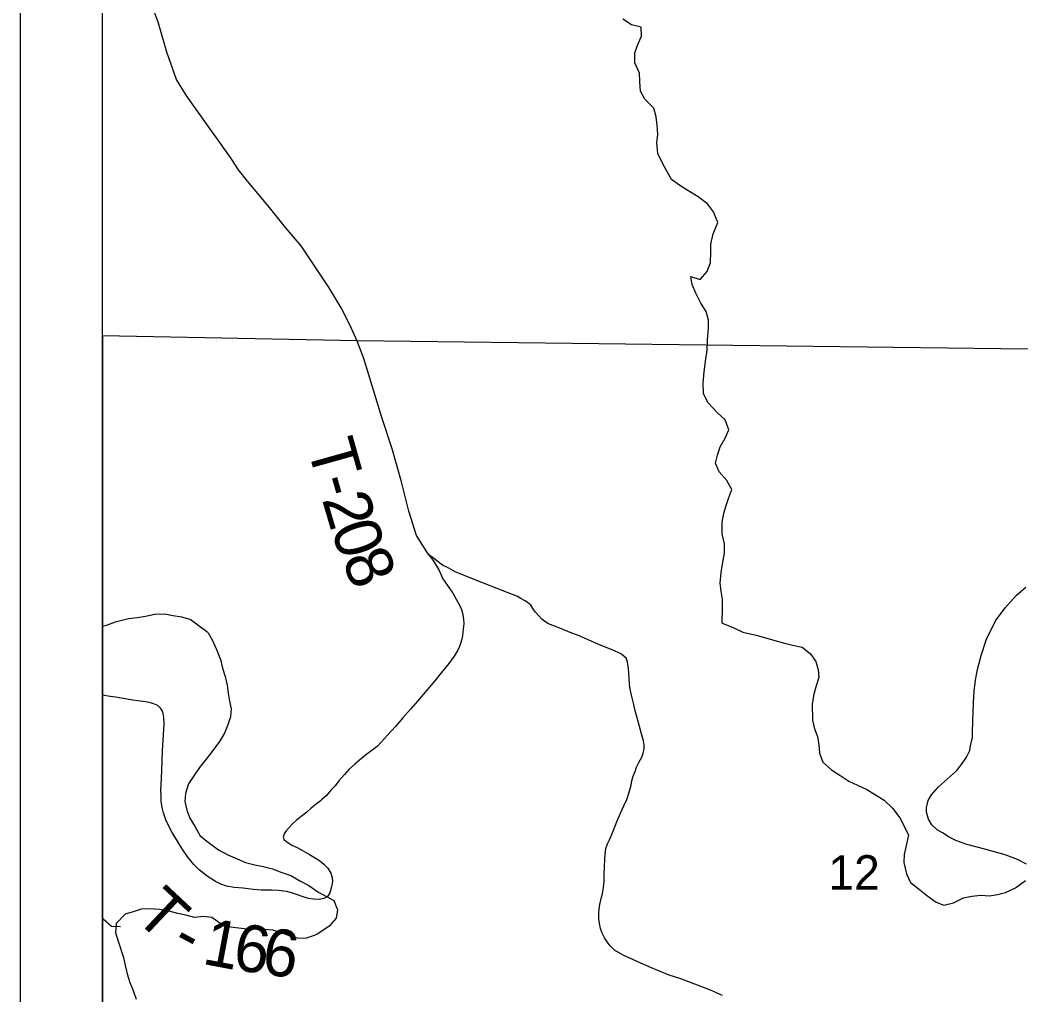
# Model space of a CAD drawing. Extents: x 0 to 34, y 0 to 22.
# Drawn here: x 2 to 3.211, y 14.917 to 16.097 of the extents above; entities that cross this region are included whole.
import ezdxf

# ---------------------------------------------------------------- set-up
doc = ezdxf.new("R2010")
doc.units = 0
for name, color, linetype in [('GM_X_Corporation', 7, 'Continuous'), ('GM_X_Minor_River', 7, 'Continuous'), ('GM_X_Section_Text', 7, 'Continuous'), ('GM_X_State_Route', 7, 'Continuous'), ('GM_X_Township_Road', 7, 'Continuous'), ('GM_X_Township_Road_Text', 7, 'Continuous'), ('SH_Data', 7, 'Continuous')]:
    doc.layers.add(name, color=color, linetype=linetype)

msp = doc.modelspace()

# ---------------------------------------------------------------- linework, layer by layer
at = {"layer": 'GM_X_Corporation'}
msp.add_lwpolyline([(2.1, 15.7148), (2.1, 14.1), (4.5503, 14.1), (4.5507, 14.1138), (4.5505, 14.2449), (4.5614, 14.6695), (4.5616, 14.6767), (4.5617, 14.6817), (4.5685, 14.9157), (4.5738, 15.1325), (4.5873, 15.6794), (4.2138, 15.6834), (3.9277, 15.6898), (3.3171, 15.6975), (2.4078, 15.7088)], close=True, dxfattribs=at)
at = {"layer": 'GM_X_Minor_River'}
for points in [[(2.8496, 15.3671), (2.8501, 15.386), (2.8499, 15.3963), (2.8483, 15.4058), (2.8474, 15.4156), (2.8484, 15.4282), (2.8505, 15.4408), (2.8526, 15.4518), (2.8525, 15.4632), (2.8496, 15.4754), (2.8498, 15.4894), (2.8516, 15.5001), (2.8545, 15.5096), (2.8578, 15.5192), (2.8615, 15.5287), (2.8552, 15.5397), (2.846, 15.5502), (2.8416, 15.5608), (2.8438, 15.5703), (2.8474, 15.5806), (2.8534, 15.591), (2.8578, 15.6013), (2.8531, 15.6134), (2.8435, 15.622), (2.8327, 15.6336), (2.8272, 15.6446), (2.8266, 15.6579), (2.828, 15.6712), (2.8293, 15.6838), (2.8314, 15.6975), (2.832, 15.7104), (2.833, 15.7237), (2.8332, 15.734), (2.8304, 15.7442), (2.8238, 15.7544), (2.8179, 15.7665), (2.8132, 15.7771), (2.8119, 15.7866), (2.823, 15.7829), (2.8313, 15.7929), (2.8357, 15.8036), (2.8359, 15.8162), (2.8358, 15.8257), (2.8386, 15.8383), (2.8442, 15.852), (2.8391, 15.8649), (2.8317, 15.8747), (2.8205, 15.8832), (2.8094, 15.8899), (2.7983, 15.897), (2.7883, 15.9041), (2.7778, 15.9233), (2.7719, 15.9358), (2.7706, 15.9491), (2.7716, 15.9586), (2.771, 15.97), (2.7698, 15.9802), (2.767, 15.9905), (2.7562, 16.0013), (2.7507, 16.0111), (2.7502, 16.0229), (2.7497, 16.0328), (2.7438, 16.0453), (2.744, 16.0574), (2.7477, 16.0674), (2.7521, 16.0777), (2.7516, 16.0887), (2.7401, 16.0912), (2.7294, 16.0983)], [(2.2276, 15.3555), (2.2168, 15.3636), (2.2057, 15.3714), (2.1958, 15.3744), (2.1851, 15.3761), (2.1752, 15.3779), (2.163, 15.3777), (2.152, 15.3753), (2.1417, 15.3736), (2.1311, 15.3723), (2.1152, 15.3683), (2.1053, 15.3648), (2.1, 15.3631)], [(2.8496, 15.3671), (2.8629, 15.3619), (2.8747, 15.3563), (2.8907, 15.3526), (2.901, 15.3496), (2.9135, 15.3459), (2.925, 15.343), (2.9349, 15.3404), (2.9463, 15.3382), (2.9562, 15.3303), (2.9631, 15.3205), (2.9659, 15.3106), (2.9667, 15.3011), (2.9634, 15.2912), (2.9604, 15.2813), (2.9586, 15.2695), (2.9588, 15.2498), (2.9612, 15.2391), (2.9651, 15.2297), (2.9667, 15.2198), (2.9675, 15.2096), (2.9714, 15.1989), (2.9821, 15.1895), (2.9932, 15.1824), (3.0031, 15.1756), (3.0134, 15.1708), (3.0245, 15.1655), (3.034, 15.1599), (3.0455, 15.1528), (3.0558, 15.143), (3.0647, 15.1313), (3.0751, 15.1108), (3.0725, 15.0994), (3.07, 15.0869), (3.0693, 15.0774), (3.0725, 15.0637), (3.0775, 15.0531), (3.0886, 15.0448), (3.0985, 15.0366), (3.1085, 15.0294), (3.118, 15.0257), (3.1294, 15.0284), (3.1415, 15.0346), (3.1517, 15.0366), (3.1627, 15.0378), (3.173, 15.0371), (3.1829, 15.0384), (3.1923, 15.0411), (3.2044, 15.0465), (3.2165, 15.0554)], [(2.2276, 15.3555), (2.2328, 15.3459), (2.2378, 15.3353), (2.2425, 15.3231), (2.2452, 15.3125), (2.2483, 15.3023), (2.2507, 15.292), (2.2519, 15.2822), (2.2535, 15.2727), (2.2555, 15.2632), (2.2548, 15.2537), (2.2515, 15.2438), (2.2474, 15.2339), (2.2414, 15.2239), (2.2335, 15.2129), (2.2252, 15.2025), (2.217, 15.1922), (2.2102, 15.1823), (2.2038, 15.1724), (2.2001, 15.1609), (2.1995, 15.151), (2.2018, 15.1408), (2.2053, 15.1309), (2.2119, 15.1204), (2.2181, 15.1098), (2.2276, 15.1019), (2.2402, 15.0928), (2.2513, 15.0868), (2.2627, 15.0816), (2.273, 15.0775), (2.2841, 15.0746), (2.2944, 15.0724), (2.3054, 15.0698), (2.3168, 15.0653), (2.3275, 15.0616), (2.3393, 15.0548), (2.3496, 15.0496), (2.3603, 15.0417), (2.3699, 15.0365), (2.3798, 15.0312), (2.3841, 15.0202), (2.3826, 15.01), (2.374, 15.0004), (2.3593, 14.99), (2.3468, 14.9857), (2.3373, 14.9853), (2.3278, 14.9879), (2.3167, 14.992), (2.306, 14.9953), (2.2954, 14.9964), (2.2829, 14.9966), (2.2718, 14.9969), (2.2612, 14.9984), (2.2517, 14.9994), (2.2418, 15.0039), (2.2322, 15.0107), (2.2219, 15.0121), (2.2113, 15.0109), (2.2006, 15.0135), (2.1911, 15.0157), (2.1805, 15.0186), (2.1687, 15.0205), (2.1565, 15.0211), (2.1466, 15.0207), (2.1368, 15.0175), (2.1273, 15.0148), (2.1164, 15.0033), (2.1157, 14.9927), (2.1189, 14.9821), (2.1251, 14.9624), (2.1271, 14.9525), (2.1298, 14.9426), (2.133, 14.932), (2.1368, 14.9222), (2.1404, 14.9119)], [(2.1, 15.0097), (2.1008, 15.009), (2.1108, 15.0004), (2.1216, 14.9997)]]:
    msp.add_lwpolyline(points, dxfattribs=at)
at = {"layer": 'GM_X_State_Route'}
msp.add_lwpolyline([(3.2178, 15.0755), (3.207, 15.0811), (3.1919, 15.0868), (3.1676, 15.0934), (3.1455, 15.0991), (3.1325, 15.1038), (3.1242, 15.1081), (3.1162, 15.1131), (3.1098, 15.1169), (3.1033, 15.1231), (3.0992, 15.1297), (3.0969, 15.1382), (3.0969, 15.1439), (3.0987, 15.1525), (3.103, 15.1594), (3.1116, 15.169), (3.1224, 15.1785), (3.133, 15.1883), (3.1393, 15.1961), (3.1454, 15.205), (3.1493, 15.213), (3.1502, 15.2185), (3.1526, 15.2286), (3.1526, 15.2356), (3.153, 15.2481), (3.1537, 15.2709), (3.1544, 15.2846), (3.156, 15.2981), (3.1584, 15.311), (3.1632, 15.3278), (3.1696, 15.3478), (3.1803, 15.3699), (3.192, 15.3855), (3.2057, 15.4009), (3.2169, 15.4107)], dxfattribs=at)
at = {"layer": 'GM_X_Township_Road'}
for points in [[(2.2547, 15.9306), (2.2109, 15.9927), (2.2009, 16.0061), (2.1892, 16.0253), (2.1777, 16.0582), (2.1677, 16.0933), (2.163, 16.1054), (2.1612, 16.1152), (2.1612, 16.1267), (2.1621, 16.1357), (2.1695, 16.1735), (2.1833, 16.2247), (2.1943, 16.2722), (2.1958, 16.2895), (2.195, 16.3043), (2.1869, 16.3755), (2.1842, 16.4343), (2.1837, 16.4743), (2.1793, 16.5039), (2.1765, 16.5529)], [(2.4944, 15.4503), (2.4799, 15.4732), (2.4706, 15.5027), (2.4617, 15.5383), (2.4505, 15.5781), (2.4377, 15.616), (2.4161, 15.6874), (2.408, 15.7083), (2.3993, 15.7273), (2.3885, 15.7487), (2.3742, 15.773), (2.3402, 15.8239), (2.3213, 15.8459), (2.3002, 15.8722), (2.2753, 15.902), (2.2645, 15.916), (2.2564, 15.9282), (2.2547, 15.9306)], [(2.4944, 15.4503), (2.4999, 15.443), (2.507, 15.4309), (2.5118, 15.4206), (2.5173, 15.4125), (2.5237, 15.4032), (2.5279, 15.3962), (2.5314, 15.3898), (2.5343, 15.3836), (2.536, 15.3775), (2.5367, 15.3714), (2.5369, 15.3667), (2.5364, 15.3599), (2.5354, 15.3518), (2.5338, 15.345), (2.5318, 15.339), (2.5298, 15.3342), (2.5255, 15.3271), (2.5187, 15.3181), (2.5098, 15.3069), (2.5021, 15.2973), (2.4808, 15.2726), (2.4727, 15.263), (2.4634, 15.2526), (2.4542, 15.2419), (2.4446, 15.2313), (2.4373, 15.2234), (2.4322, 15.2179), (2.4259, 15.213), (2.4197, 15.2084), (2.4109, 15.2014), (2.405, 15.1964), (2.3984, 15.1904), (2.3927, 15.184), (2.3859, 15.1763), (2.3812, 15.17), (2.3766, 15.1651), (2.3709, 15.1585), (2.365, 15.1532), (2.363, 15.1515), (2.3617, 15.1505)], [(2.8499, 14.9165), (2.8355, 14.9226), (2.8196, 14.929), (2.7996, 14.9363), (2.7853, 14.9411), (2.7622, 14.9506), (2.7466, 14.9576), (2.7297, 14.9653), (2.7194, 14.9714), (2.7143, 14.9763), (2.7103, 14.9811), (2.7071, 14.9862), (2.7046, 14.9919), (2.7026, 14.9976), (2.7013, 15.0035), (2.7005, 15.0095), (2.7004, 15.0158), (2.7007, 15.0209), (2.7018, 15.0264), (2.7037, 15.0352), (2.7049, 15.0394), (2.706, 15.0475), (2.7068, 15.0541), (2.707, 15.0624), (2.7073, 15.0715), (2.7077, 15.0812), (2.7082, 15.0875), (2.709, 15.0941), (2.7108, 15.1001), (2.7132, 15.1047), (2.7176, 15.1154), (2.7227, 15.1277), (2.7268, 15.1372), (2.7306, 15.146), (2.7341, 15.1535), (2.737, 15.1625), (2.7396, 15.1711), (2.7403, 15.1763), (2.742, 15.182), (2.7444, 15.1876), (2.7458, 15.1926), (2.7493, 15.1992), (2.7524, 15.2047), (2.7541, 15.2098), (2.7554, 15.2148), (2.7552, 15.2197), (2.7543, 15.2245), (2.7519, 15.2329), (2.7468, 15.2524), (2.7444, 15.2608), (2.7427, 15.2687), (2.7405, 15.2781), (2.7385, 15.2871), (2.7376, 15.2929), (2.7369, 15.3003), (2.7365, 15.3063), (2.7361, 15.3127), (2.7354, 15.3171), (2.735, 15.3203), (2.7334, 15.3245), (2.731, 15.3269), (2.7279, 15.3296), (2.7238, 15.3316), (2.7167, 15.3348), (2.7013, 15.3408), (2.6765, 15.3516), (2.6659, 15.3559), (2.6552, 15.3601), (2.6468, 15.3636), (2.6395, 15.3663), (2.6349, 15.3689), (2.6314, 15.3718), (2.6277, 15.3758), (2.6239, 15.3804), (2.6204, 15.3848), (2.618, 15.3889), (2.6141, 15.392), (2.6114, 15.394), (2.6061, 15.3969), (2.6011, 15.3997), (2.5908, 15.4037), (2.5477, 15.4208), (2.5367, 15.425), (2.5266, 15.4294), (2.518, 15.434), (2.5112, 15.4371), (2.5061, 15.4412), (2.5004, 15.4459), (2.4944, 15.4503)], [(2.1929, 15.0993), (2.1904, 15.1033), (2.1843, 15.1135), (2.1796, 15.122), (2.1763, 15.1289), (2.1735, 15.1376), (2.1721, 15.144), (2.1708, 15.1511), (2.1706, 15.1585), (2.1704, 15.1651), (2.1706, 15.1715), (2.1717, 15.1887), (2.1726, 15.2124), (2.1744, 15.2452), (2.1741, 15.2528), (2.1733, 15.2577), (2.1722, 15.2614), (2.17, 15.2641), (2.1666, 15.2674), (2.1609, 15.27), (2.1546, 15.2713), (2.1367, 15.274), (2.1222, 15.2761), (2.1154, 15.2775), (2.109, 15.2784), (2.1, 15.2798)], [(2.3617, 15.1505), (2.3582, 15.1478), (2.3524, 15.1432), (2.3469, 15.1383), (2.3401, 15.133), (2.3342, 15.128), (2.3296, 15.124), (2.3256, 15.1198), (2.3219, 15.1157), (2.3197, 15.1122), (2.3183, 15.1078), (2.3197, 15.1047), (2.3241, 15.1014), (2.3291, 15.0985), (2.3353, 15.0956), (2.3417, 15.0917), (2.3502, 15.0869), (2.3623, 15.0796), (2.3676, 15.0752), (2.3724, 15.0706), (2.3762, 15.0646), (2.3779, 15.0587), (2.3781, 15.0545), (2.3768, 15.048), (2.3749, 15.0407), (2.372, 15.0361), (2.3678, 15.0337), (2.3623, 15.0326), (2.3551, 15.0328), (2.3491, 15.0339), (2.3425, 15.0359), (2.3357, 15.0383), (2.3287, 15.0407), (2.3225, 15.0424), (2.3127, 15.0436), (2.3043, 15.044), (2.292, 15.044), (2.2821, 15.0447), (2.27, 15.0462), (2.259, 15.0471), (2.2498, 15.0486), (2.243, 15.051), (2.2366, 15.0543), (2.2265, 15.0609), (2.2166, 15.0684), (2.2102, 15.075), (2.2032, 15.0836), (2.1972, 15.0928), (2.1929, 15.0993)]]:
    msp.add_lwpolyline(points, dxfattribs=at)
at = {"layer": 'SH_Data'}
msp.add_line((2, 21), (2, 14), dxfattribs=at)
msp.add_lwpolyline([(2.1, 20.9), (8.9, 20.9), (8.9, 14.1), (2.1, 14.1)], close=True, dxfattribs=at)

# ---------------------------------------------------------------- texts
at = {"layer": 'GM_X_Section_Text'}
msp.add_text('12', height=0.04186, rotation=0, dxfattribs=at).set_placement((2.9781, 15.0443))
at = {"layer": 'GM_X_Township_Road_Text'}
for s, rotation, p in [('T', 285.7329, (2.3471, 15.5812)), ('-', 285.8788, (2.3587, 15.5402)), ('2', 286.4628, (2.3652, 15.5171)), ('0', 288.5172, (2.3758, 15.4815)), ('8', 293.0071, (2.3887, 15.4437)), ('T', 316.8216, (2.1367, 15.0108)), ('1', 349.3177, (2.2191, 14.9549)), ('6', 351.6806, (2.2561, 14.948)), ('6', 351.8991, (2.2909, 14.9429)), ('-', 331.7802, (2.1808, 14.9723))]:
    msp.add_text(s, height=0.0568, rotation=rotation, dxfattribs=at).set_placement(p)

doc.saveas('drawing.dxf')
